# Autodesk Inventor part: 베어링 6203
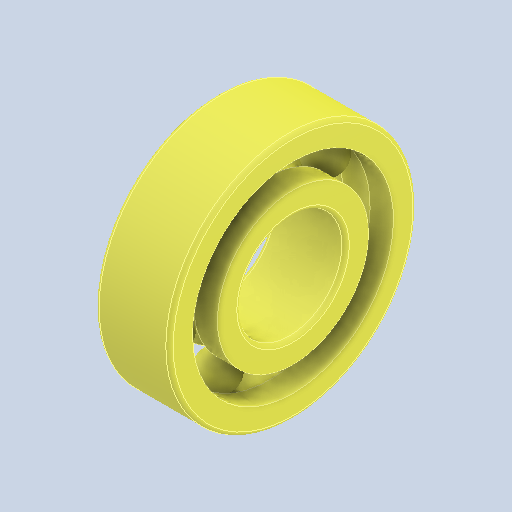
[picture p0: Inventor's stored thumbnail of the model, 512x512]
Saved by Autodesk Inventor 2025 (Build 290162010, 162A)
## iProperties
Created: 2024-07
Part Number: 베어링 6203
Material: 강철, 연강
Description: 깊은 그루브 볼 베어링
Document SubType Name: Modeling
Designer: 계정
Density: 7.86 g/cm^3
Appearance: 기본값
Author: jhkim
Revision Number: 1
Sending System: Autodesk Inventor 2025
Preprocessor: ST-DEVELOPER v20
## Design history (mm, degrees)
feature "Solid1"
feature "Solid1:1"
feature "Solid1:2"
feature "Solid1:3"
feature "Solid1:4"
feature "Solid1:5"
feature "Solid1:6"
feature "Solid1:7"
feature "Solid1:8"
node "솔리드1"
node "솔리드2"
node "솔리드3"
node "솔리드4"
node "솔리드5"
node "솔리드6"
node "솔리드7"
node "솔리드8"
node "솔리드9"
